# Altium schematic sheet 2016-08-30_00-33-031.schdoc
size 251 x 132 mm; SheetNumber: 1; SheetTotal: 1
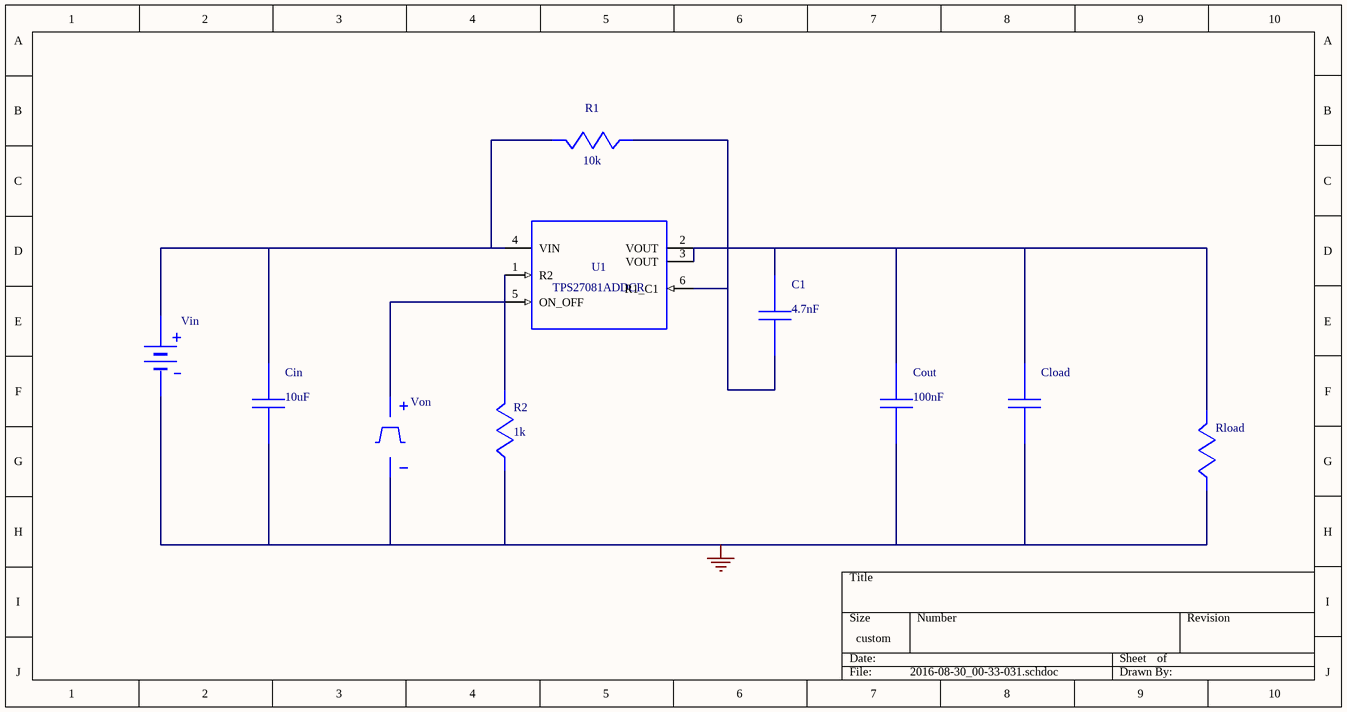
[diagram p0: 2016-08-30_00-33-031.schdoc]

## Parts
C1  value 4.7nF  (hidden comment: CC0805KRX7R9BB472)
Cin  value 10uF  (hidden comment: GRM219R60J106KE19D)
Cload  GRM21BR71E104KA01L  (value not drawn)
Cout  value 100nF  (hidden comment: GRM155R60J104KA01D)
R1  value 10k  (hidden comment: CRCW040210K0FKED)
R2  value 1k  (hidden comment: CRCW04021K00FKED)
Rload  WB_LOAD_RESISTOR  (value not drawn)
U1  TPS27081ADDCR
Vin  WB_BATTERY  (value not drawn)
Von  WB_PRIM_PWL_VOLTAGE_SOURCE  (value not drawn)

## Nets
0: Cin.2 Cload.2 Cout.2 R2.2 Rload.2 Vin.2(-) Von.2(-)
NetC1_1: C1.1 Cload.1 Cout.1 Rload.1 U1.2(VOUT) U1.3(VOUT)
NetC1_2: C1.2 R1.2 U1.6(R1_C1)
NetCin_1: Cin.1 R1.1 U1.4(VIN) Vin.1(+)
NetR2_1: R2.1 U1.1(R2) U1.5(ON_OFF) Von.1(+)

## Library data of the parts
C1 = CC0805KRX7R9BB472: CC0805KRX7R9BB47; Manufacturer Name: Yageo America
Cin = GRM219R60J106KE19D: GRM219R60J106KE1; Manufacturer Name: MuRata
Cload = GRM21BR71E104KA01L: WB_PRIMITIVE_CAP; Manufacturer Name: WB_PRIMITIVE_CAPACITOR
Cout = GRM155R60J104KA01D: GRM155R60J104KA0; Manufacturer Name: MuRata
R1 = CRCW040210K0FKED: Manufacturer Name: Vishay-Dale
R2 = CRCW04021K00FKED: Manufacturer Name: Vishay-Dale
U1 = TPS27081ADDCR: Manufacturer Name: Texas Instruments
Von = WB_PRIM_PWL_VOLTAGE_SOURCE: WB_PRIM_PWL_VOLT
